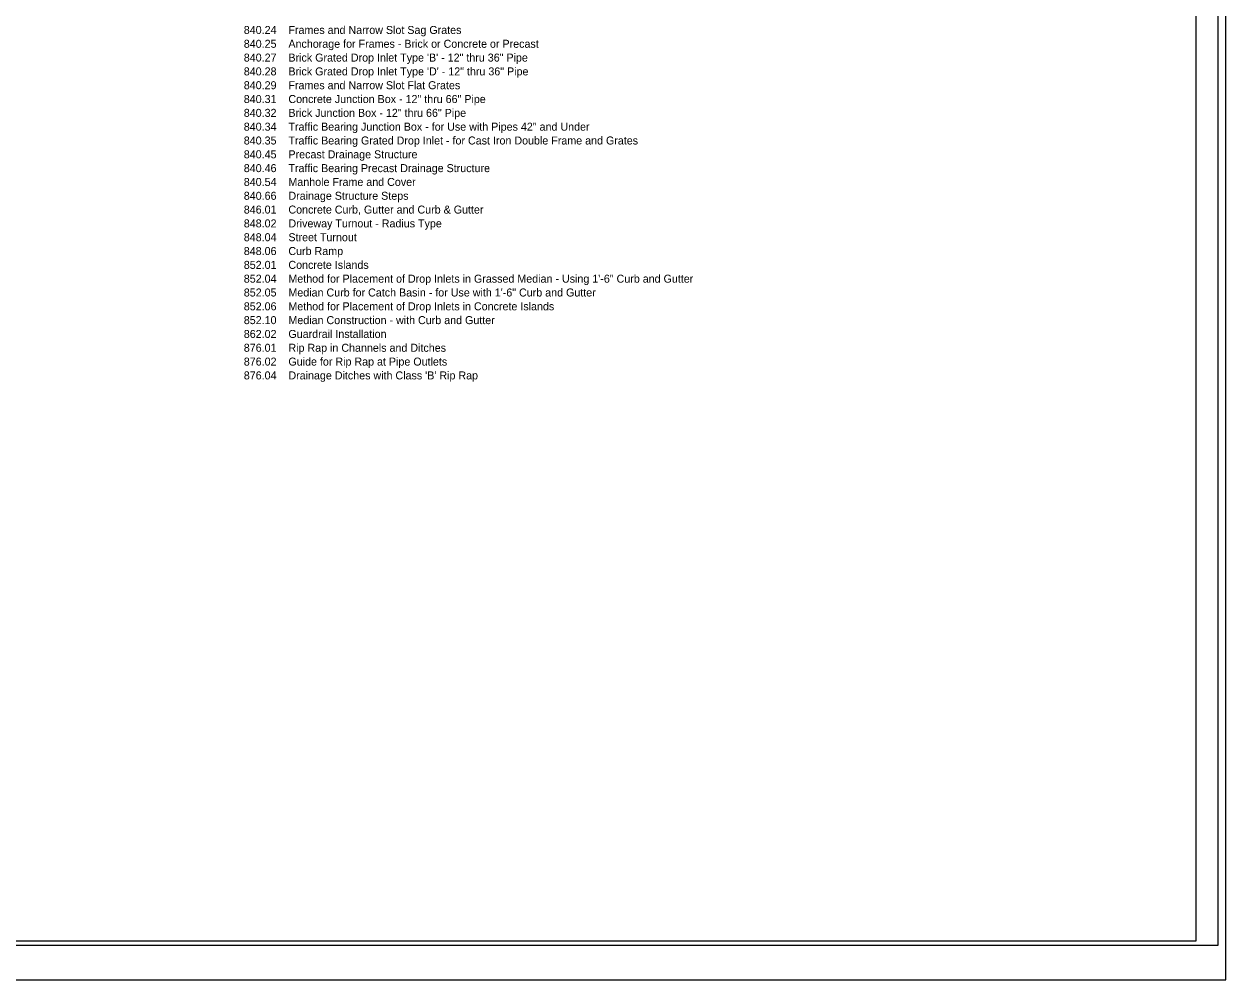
# Model space of a CAD drawing. Extents: x 1877070 to 1879304, y 464355 to 465670.
# Drawn here: x 1878265 to 1879091, y 464355 to 465012 of the extents above; entities that cross this region are included whole.
import ezdxf

# ---------------------------------------------------------------- set-up
doc = ezdxf.new("R2010")
doc.units = 0
for name, color, linetype in [('Prop AutoTurn Projected Path', 7, 'Continuous'), ('Prop Horizontal Alignment', 7, 'Continuous'), ('Prop Lane Lines', 7, 'Continuous'), ('Scratch_Level_0', 7, 'Continuous')]:
    doc.layers.add(name, color=color, linetype=linetype)

msp = doc.modelspace()

# ---------------------------------------------------------------- linework, layer by layer
at = {"layer": 'Prop AutoTurn Projected Path'}
msp.add_lwpolyline([(1877069.97, 464355.13), (1879090.77, 464355.13), (1879090.77, 465669.52), (1877069.97, 465669.52)], close=True, dxfattribs=at)
at = {"layer": 'Prop Lane Lines'}
msp.add_lwpolyline([(1877085.58, 464379.14), (1879085.37, 464379.14), (1879085.37, 465645.52), (1877085.58, 465645.52)], close=True, dxfattribs=at)
at = {"layer": 'Scratch_Level_0'}
msp.add_lwpolyline([(1879070.37, 465642.52), (1877269.83, 465642.52), (1877269.83, 464382.14), (1879070.37, 464382.14)], close=True, dxfattribs=at)

# ---------------------------------------------------------------- texts
at = {"layer": 'Prop Horizontal Alignment'}
for s, p in [('840.24    Frames and Narrow Slot Sag Grates', (1878415.62, 465005.59)), ('840.25    Anchorage for Frames - Brick or Concrete or Precast', (1878415.62, 464996.09)), ('840.27    Brick Grated Drop Inlet Type \'B\' - 12" thru 36" Pipe', (1878415.62, 464986.59)), ('840.28    Brick Grated Drop Inlet Type \'D\' - 12" thru 36" Pipe', (1878415.62, 464977.09)), ('840.29    Frames and Narrow Slot Flat Grates', (1878415.62, 464967.59)), ('840.31    Concrete Junction Box - 12" thru 66" Pipe', (1878415.62, 464958.09)), ('840.32    Brick Junction Box - 12" thru 66" Pipe', (1878415.62, 464948.59)), ('840.34    Traffic Bearing Junction Box - for Use with Pipes 42" and Under', (1878415.62, 464939.08)), ('840.35    Traffic Bearing Grated Drop Inlet - for Cast Iron Double Frame and Grates', (1878415.62, 464929.58)), ('840.45    Precast Drainage Structure', (1878415.62, 464920.08)), ('840.46    Traffic Bearing Precast Drainage Structure', (1878415.62, 464910.58)), ('840.54    Manhole Frame and Cover', (1878415.62, 464901.08)), ('840.66    Drainage Structure Steps', (1878415.62, 464891.58)), ('846.01    Concrete Curb, Gutter and Curb & Gutter', (1878415.62, 464882.08)), ('848.02    Driveway Turnout - Radius Type', (1878415.62, 464872.58)), ('848.04    Street Turnout', (1878415.62, 464863.07)), ('848.06    Curb Ramp', (1878415.62, 464853.57)), ('852.01    Concrete Islands', (1878415.62, 464844.07)), ('852.04    Method for Placement of Drop Inlets in Grassed Median - Using 1\'-6" Curb and Gutter', (1878415.62, 464834.57)), ('852.05    Median Curb for Catch Basin - for Use with 1\'-6" Curb and Gutter', (1878415.62, 464825.07)), ('852.06    Method for Placement of Drop Inlets in Concrete Islands', (1878415.62, 464815.57)), ('852.10    Median Construction - with Curb and Gutter', (1878415.62, 464806.07)), ('862.02    Guardrail Installation', (1878415.62, 464796.57)), ('876.01    Rip Rap in Channels and Ditches', (1878415.62, 464787.07)), ('876.02    Guide for Rip Rap at Pipe Outlets', (1878415.62, 464777.56)), ("876.04    Drainage Ditches with Class 'B' Rip Rap", (1878415.62, 464768.06))]:
    msp.add_text(s, height=5.5, dxfattribs=at).set_placement(p)

doc.saveas('drawing.dxf')
